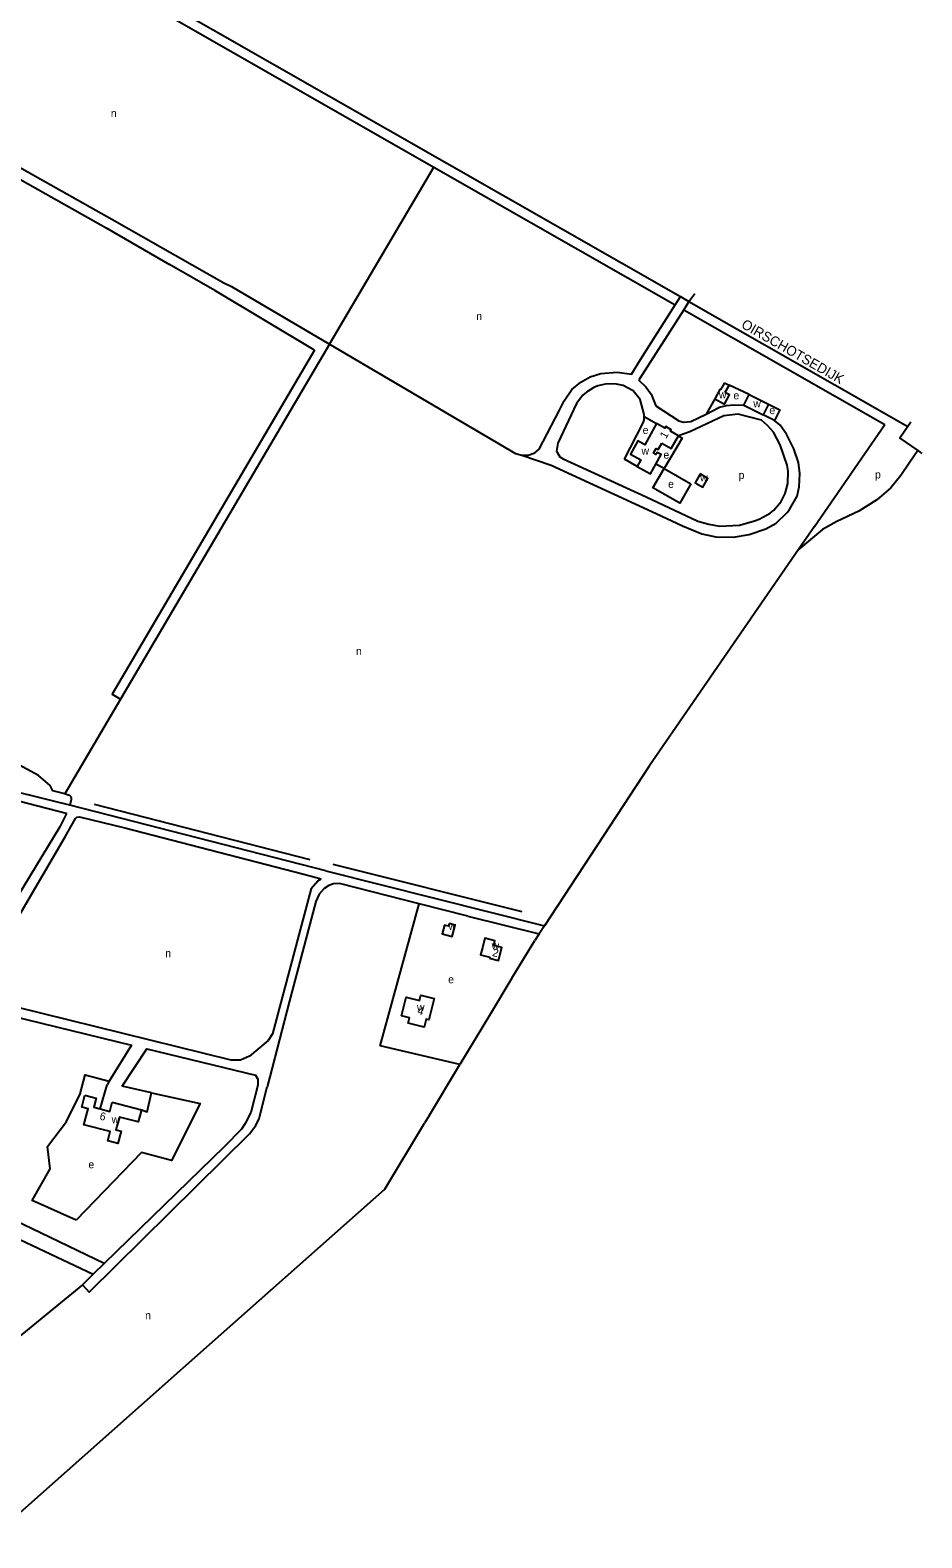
# Model space of a CAD drawing. Extents: x 156521 to 159067, y 384230 to 386095.
# Drawn here: x 158613 to 159067, y 384432 to 385200 of the extents above; entities that cross this region are included whole.
import ezdxf

# ---------------------------------------------------------------- set-up
doc = ezdxf.new("R2010")
doc.units = 0
for name, color, linetype in [('BLT_Basislijn', 7, 'Continuous'), ('BLT_Bebouwing', 7, 'Continuous'), ('BLT_Centroide', 7, 'Continuous'), ('BLT_Huisnummer', 7, 'Continuous'), ('BLT_Straatnaam', 7, 'Continuous'), ('BLT_Vlakafsluiter', 7, 'Continuous')]:
    doc.layers.add(name, color=color, linetype=linetype)

msp = doc.modelspace()

# ---------------------------------------------------------------- linework, layer by layer
at = {"layer": 'BLT_Basislijn'}
for p, q in [((158588.51, 385261.81), (158818.33, 385130.52)), ((158594.43, 385264.19), (158943.9, 385064.55)), ((158765.14, 385040.3), (158818.33, 385130.52)), ((158818.33, 385130.52), (158941.2, 385060.33)), ((158943.9, 385064.55), (158948.24, 385062.06)), ((158948.24, 385062.06), (159059.68, 384998.41)), ((158945.55, 385057.84), (159048.01, 384999.31)), ((158765.14, 385040.3), (158658.77, 384859.51)), ((158978.86, 385014.67), (158968.65, 385019.42)), ((158961.38, 385012.45), (158957, 385004.72)), ((158925.44, 385003.38), (158931.72, 384999.95)), ((158991.89, 385001.41), (158986, 385004.36)), ((159012.14, 384947.36), (159048.01, 384999.31)), ((158658.77, 384859.51), (158630.36, 384811.22)), ((158632.84, 384805.48), (158625.27, 384807.42)), ((158763.29, 384772), (158632.84, 384805.48)), ((158645.22, 384806), (158755.21, 384777.84)), ((158752.07, 384770.33), (158760.97, 384768.02)), ((158763.29, 384772), (158874.6, 384743.97)), ((158766.87, 384775.43), (158863.14, 384751.37)), ((158755.84, 384763.05), (158736.06, 384689.06)), ((158810.88, 384755.27), (158770.26, 384765.51)), ((158791.04, 384682.85), (158810.88, 384755.27)), ((158835.68, 384749.01), (158810.88, 384755.27)), ((158835.68, 384749.01), (158871.92, 384739.88)), ((158871.92, 384739.88), (158869.75, 384736.58)), ((158874.6, 384743.97), (158871.92, 384739.88)), ((158858.06, 384717.34), (158869.75, 384736.58)), ((158858.06, 384717.34), (158847.24, 384699.25)), ((158847.24, 384699.25), (158831.61, 384673.45)), ((158816.1, 384647.64), (158831.61, 384673.45)), ((158648.42, 384650.79), (158651.87, 384663.05)), ((158653.02, 384664.92), (158651.87, 384663.05)), ((158674.52, 384658.95), (158659.63, 384662.37)), ((158734.79, 384667.05), (158733.46, 384662)), ((158816.1, 384647.64), (158813.53, 384643.43)), ((158650.46, 384571.96), (158589.98, 384600.98)), ((158650.46, 384571.96), (158644.87, 384566.51)), ((158644.87, 384566.51), (158639.35, 384561.14)), ((158639.35, 384561.14), (158546.61, 384485.51)), ((158655.78, 384487.93), (158669.4, 384500)), ((158592.98, 384432.27), (158655.78, 384487.93))]:
    msp.add_line(p, q, dxfattribs=at)
for points in [[(158528.66, 385174.61), (158654.35, 385103.98), (158711.3, 385071.58), (158715.21, 385069.61), (158765.14, 385040.3)], [(158539.39, 385162.51), (158545.74, 385158.98), (158651.48, 385099.52), (158683.59, 385080.92)], [(158757.53, 385037.22), (158706.77, 385067.6), (158683.59, 385080.92)], [(158941.2, 385060.33), (158943.9, 385064.55)], [(158948.24, 385062.06), (158945.55, 385057.84)], [(158863.09, 384983.71), (158866.34, 384983.71), (158869.78, 384984.89), (158872.01, 384986.8), (158882.37, 385006.64), (158884.65, 385011.51), (158888.56, 385017.21), (158893.24, 385020.95), (158897.9, 385023.59), (158903.44, 385025.31), (158911.65, 385025.98), (158919.01, 385025.07), (158923.5, 385032.56), (158941.2, 385060.33)], [(158945.55, 385057.84), (158922.85, 385022.24), (158922.85, 385021.87), (158926.29, 385018.5), (158929, 385014.76), (158931.43, 385008.82), (158943.16, 385001.23), (158945.39, 385000.51), (158949.28, 385000.88), (158957, 385004.72)], [(158765.14, 385040.3), (158859.97, 384984.62), (158863.09, 384983.71)], [(158757.53, 385037.22), (158654.46, 384862.04), (158658.77, 384859.51)], [(158925.44, 385003.38), (158925.36, 385004.42), (158923.43, 385012.05), (158919.86, 385016.6), (158914.77, 385019.17), (158911.31, 385019.96), (158906.39, 385020.17), (158901.79, 385019.09), (158899.71, 385018.26), (158895.98, 385015.87), (158894.22, 385014.37), (158890.98, 385010.06), (158881.4, 384989.86), (158880.8, 384985.78), (158882.51, 384982.87), (158884.11, 384981.87), (158926.53, 384962.52), (158952.78, 384950.19), (158958.32, 384948.66), (158963.86, 384947.66), (158973.98, 384948.14), (158981.62, 384950.22), (158984.07, 384951.21), (158989.66, 384954.2), (158991.4, 384955.78), (158995.22, 384960.16), (158997.29, 384964.23), (158998.67, 384969.32), (158998.71, 384975.56), (158998.34, 384978.72), (158994.69, 384989.01), (158991.33, 384995.51), (158988.32, 384998.86), (158985.19, 385001.61), (158973.25, 385004.65), (158965.93, 385003.71), (158948.77, 384995.66), (158942.9, 384993.62)], [(158957, 385004.72), (158963.86, 385008.13), (158967.3, 385009.06), (158971.12, 385009.47), (158976.16, 385009.28)], [(158988.7, 385009.75), (158994.58, 385006.81), (158991.89, 385001.41)], [(158915.37, 384981.65), (158924.72, 384999.96), (158925.51, 385001.66), (158925.49, 385002.59), (158925.44, 385003.38)], [(158931.54, 384954.04), (158944.88, 384947.8), (158954.78, 384943.65), (158961.95, 384942.17), (158970.93, 384941.93), (158978.98, 384943.28), (158987.36, 384946.15), (158992.61, 384949.17), (158998.24, 384954.58), (158999.41, 384956.13), (159003.27, 384962.93), (159004.45, 384967.54), (159004.77, 384974.45), (159003.97, 384980.05), (159001.74, 384987.06), (158997.89, 384994.5), (158994.62, 384999.08), (158991.89, 385001.41)], [(158942.9, 384993.62), (158944.74, 384992.46), (158935.57, 384976.9)], [(159059.68, 384998.41), (159055.57, 384992.42), (159064.79, 384986.08)], [(158863.09, 384983.71), (158878.12, 384978.72), (158931.54, 384954.04)], [(159064.79, 384986.08), (159060.38, 384979.65), (159056.19, 384973.37), (159051.05, 384967.06), (159043.96, 384961.05), (159034.7, 384955.23), (159023.49, 384949.99), (159016.31, 384945.83), (159004.06, 384935.64)], [(158921.82, 384978.04), (158915.37, 384981.65)], [(158921.82, 384978.04), (158915.37, 384981.65)], [(158949.26, 384969.14), (158943.66, 384959.25), (158929.87, 384967.07), (158935.57, 384976.9)], [(158935.57, 384976.9), (158931.32, 384979.14)], [(158935.57, 384976.9), (158949.26, 384969.14)], [(159012.14, 384947.36), (159004.06, 384935.64)], [(159004.06, 384935.64), (158927.98, 384825.33), (158874.6, 384743.97)], [(158342.81, 384770.73), (158333.64, 384773.36), (158283.17, 384786.22), (158282.77, 384787.06), (158335.72, 384877.79), (158631, 384801.39), (158631.05, 384800.83), (158627.73, 384794.49), (158603.23, 384753.88), (158602.28, 384751.89), (158580.79, 384715.97), (158576.88, 384709.55), (158576.56, 384709.5), (158462.13, 384739.64), (158349.17, 384768.98)], [(158625.27, 384807.42), (158597.16, 384814.34), (158383.51, 384870.65)], [(158630.36, 384811.22), (158624.21, 384812.78), (158622.82, 384815.52), (158616.96, 384820.59), (158590.84, 384834.71)], [(158630.36, 384811.22), (158632.15, 384810.76), (158632.8, 384810.49), (158633.46, 384809.83), (158633.67, 384809.11), (158633.57, 384808.31), (158632.84, 384805.48)], [(158736.06, 384689.06), (158733.97, 384685.58), (158724.47, 384677.61), (158719.79, 384675.59), (158715, 384675.59), (158591.18, 384706.23), (158587.23, 384707.3), (158586.12, 384707.91), (158585.24, 384709.01), (158585.48, 384712.56), (158630.6, 384789.27), (158635.77, 384798.67), (158636.48, 384799.41), (158637.85, 384799.54), (158660.96, 384793.85), (158752.07, 384770.33)], [(158770.26, 384765.51), (158767.26, 384765.39), (158764.85, 384764.57), (158762.47, 384763.03), (158759.9, 384760.1), (158758.19, 384756.44), (158744.65, 384705.15), (158734.79, 384667.05)], [(158755.84, 384763.05), (158759.17, 384766.85), (158760.97, 384768.02)], [(158535.23, 384626.42), (158561.09, 384670.52), (158580.13, 384703.71), (158664.3, 384683.31), (158653.02, 384664.92)], [(158659.63, 384662.37), (158672.12, 384681.41), (158727.42, 384668.01), (158728.59, 384665.95), (158728.71, 384662.79)], [(158831.61, 384673.45), (158791.04, 384682.85)], [(158636.1, 384594.02), (158613.68, 384604.1), (158622.93, 384620.29), (158621.54, 384631.62), (158631.25, 384644.33), (158638.16, 384658.42), (158640.7, 384668.17), (158653.02, 384664.92)], [(158639.35, 384561.14), (158642.76, 384557.49), (158724.45, 384638.03), (158727.63, 384642.33), (158729.38, 384645.93), (158733.46, 384662)], [(158728.71, 384662.79), (158725.08, 384648.95), (158722.18, 384643.24), (158720.27, 384640.44), (158711.56, 384631.43), (158650.46, 384571.96)], [(158674.52, 384658.95), (158699.23, 384653.58), (158684.63, 384624.42), (158669.46, 384628.61), (158636.1, 384594.02)], [(158669.35, 384650.29), (158672.23, 384649.34), (158674.52, 384658.95)], [(158690.62, 384518.82), (158793.37, 384609.89), (158813.53, 384643.43)], [(158597.08, 384573.54), (158607.52, 384584.17), (158644.87, 384566.51)], [(158669.4, 384500), (158690.62, 384518.82)]]:
    msp.add_lwpolyline(points, dxfattribs=at)
at = {"layer": 'BLT_Bebouwing'}
for p, q in [((158966.42, 385020.68), (158964.31, 385016.95)), ((158966.42, 385020.68), (158968.65, 385019.42)), ((158968.65, 385019.42), (158966.57, 385015.74)), ((158978.86, 385014.67), (158988.7, 385009.75)), ((158976.16, 385009.28), (158986, 385004.36)), ((158988.7, 385009.75), (158986, 385004.36)), ((158654.53, 384654.15), (158669.35, 384650.29))]:
    msp.add_line(p, q, dxfattribs=at)
for points in [[(158964.31, 385016.95), (158963.93, 385017.16), (158961.38, 385012.45)], [(158961.38, 385012.45), (158966.31, 385009.79), (158968.85, 385014.5), (158966.57, 385015.74)], [(158976.16, 385009.28), (158978.86, 385014.67)], [(158931.72, 384999.95), (158925.82, 384989.06), (158922.22, 384991.08), (158918.42, 384984.29), (158923.68, 384981.34), (158921.82, 384978.04)], [(158942.9, 384993.62), (158938.76, 384995.93), (158939.22, 384996.74), (158936.42, 384998.31), (158936, 384997.55), (158931.72, 384999.95)], [(158934.37, 384989.79), (158939.22, 384987.07), (158942.9, 384993.62)], [(158931.32, 384979.14), (158934.06, 384984.02), (158932.07, 384985.14), (158931.44, 384984.02), (158930.13, 384984.75), (158930.76, 384985.87), (158931.51, 384987.21), (158932.59, 384986.61), (158934.37, 384989.79)], [(158921.82, 384978.04), (158928.58, 384974.25), (158931.32, 384979.14)], [(158826.13, 384745.27), (158825.73, 384743.79), (158823.67, 384744.35), (158822.5, 384740), (158827.67, 384738.61), (158829.24, 384744.43), (158826.13, 384745.27)], [(158846.66, 384727.5), (158851.17, 384726.33), (158852.92, 384732.98), (158848.83, 384734.06), (158849.44, 384736.37), (158844.35, 384737.71), (158843.07, 384732.88), (158842.12, 384729.26), (158846.78, 384728.02), (158846.66, 384727.5)], [(158801.9, 384698.18), (158804.29, 384707.68), (158811.07, 384705.96), (158811.75, 384708.67), (158818.54, 384706.96), (158815.8, 384696.1), (158814.44, 384696.43), (158813.42, 384692.36), (158805.28, 384694.44), (158805.97, 384697.15), (158801.9, 384698.18)], [(158669.35, 384650.29), (158667.72, 384644.13), (158658.12, 384646.57), (158656.41, 384640.05), (158659.02, 384639.38), (158657.4, 384633.2), (158652.23, 384634.57), (158653.44, 384639.28), (158640.05, 384642.69), (158642.2, 384650.81), (158639.02, 384651.67), (158640.59, 384657.79)], [(158640.59, 384657.79), (158646.39, 384656.28), (158645.18, 384651.63), (158648.42, 384650.79)], [(158648.42, 384650.79), (158653.32, 384649.51), (158654.53, 384654.15)]]:
    msp.add_lwpolyline(points, dxfattribs=at)
msp.add_lwpolyline([(158953.95, 384974.16), (158951.43, 384969.72), (158955.35, 384967.51), (158957.86, 384971.94)], close=True, dxfattribs=at)
at = {"layer": 'BLT_Vlakafsluiter'}
for p, q in [((158948.24, 385062.06), (158951.29, 385066.08)), ((159061.2, 385000.62), (159059.68, 384998.41)), ((159064.79, 384986.08), (159066.86, 384984.67))]:
    msp.add_line(p, q, dxfattribs=at)

# ---------------------------------------------------------------- texts
at = {"layer": 'BLT_Centroide'}
for s, p in [('n', (158653.78, 385155.99)), ('n', (158839.89, 385052.59)), ('w', (158963.48, 385012.63)), ('e', (158970.9, 385012.22)), ('w', (158981.01, 385008.11)), ('e', (158989.18, 385004.66)), ('e', (158924.65, 384994.55)), ('w', (158924.06, 384984)), ('e', (158935.24, 384981.96)), ('e', (158937.61, 384967.07)), ('w', (158953.93, 384970.36)), ('p', (158973.53, 384971.64)), ('p', (159043.01, 384971.89)), ('n', (158778.64, 384881.9)), ('w', (158825.79, 384741.94)), ('n', (158681.51, 384728.04)), ('w', (158847.76, 384732.03)), ('e', (158825.6, 384714.75)), ('w', (158809.7, 384700.53)), ('w', (158654.19, 384643.45)), ('e', (158642.37, 384620.5)), ('n', (158671.25, 384543.64))]:
    msp.add_text(s, height=4, dxfattribs=at).set_placement(p)
at = {"layer": 'BLT_Huisnummer'}
for s, rotation, p in [('1', 60.7312, (158936.6, 384991.84)), ('2', 345.50394, (158847.8, 384728.72)), ('4', 345.70737, (158809.63, 384699.11)), ('6', 346.20072, (158647.8, 384645.38))]:
    msp.add_text(s, height=4, rotation=rotation, dxfattribs=at).set_placement(p)
at = {"layer": 'BLT_Straatnaam'}
msp.add_text('OIRSCHOTSEDIJK', height=5, rotation=330.13863, dxfattribs=at).set_placement((158974.47, 385048.98))

doc.saveas('drawing.dxf')
